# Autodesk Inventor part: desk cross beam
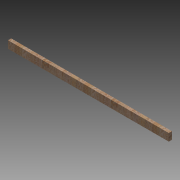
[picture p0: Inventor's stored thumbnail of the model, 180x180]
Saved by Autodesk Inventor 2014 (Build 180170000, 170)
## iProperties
Created: 2013-07
Part Number: desk cross beam
Material: Generic
Document SubType Name: Modeling
Designer: Patrick Rice
Density: 1 g/cm^3
Appearance: Red Oak - Natural
Author: Patrick Rice
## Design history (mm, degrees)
sketch "Sketch2"
  geometry: L1 (44.45, -19.05)-(-44.45, -19.05); L2 (-44.45, -19.05)-(-44.45, 19.05); L3 (-44.45, 19.05)-(44.45, 19.05); L4 (44.45, 19.05)-(44.45, -19.05); L5 (44.45, -19.05)-(-44.45, 19.05); L6 (-44.45, -19.05)-(44.45, 19.05); 1 further point
  constraints: 12 end point, 2 midpoint, 2 parallel, 1 horizontal, 1 perpendicular
  dimensions: "d4" = 88.9 distance of L2.end L3.end; "d5" = 38.1 distance of L1.end L2.end
extrude "Extrusion2" new body sketch "Sketch2" distance "d6" = 1930.4; taper "d7" = 0 deg
body "Solid2"
